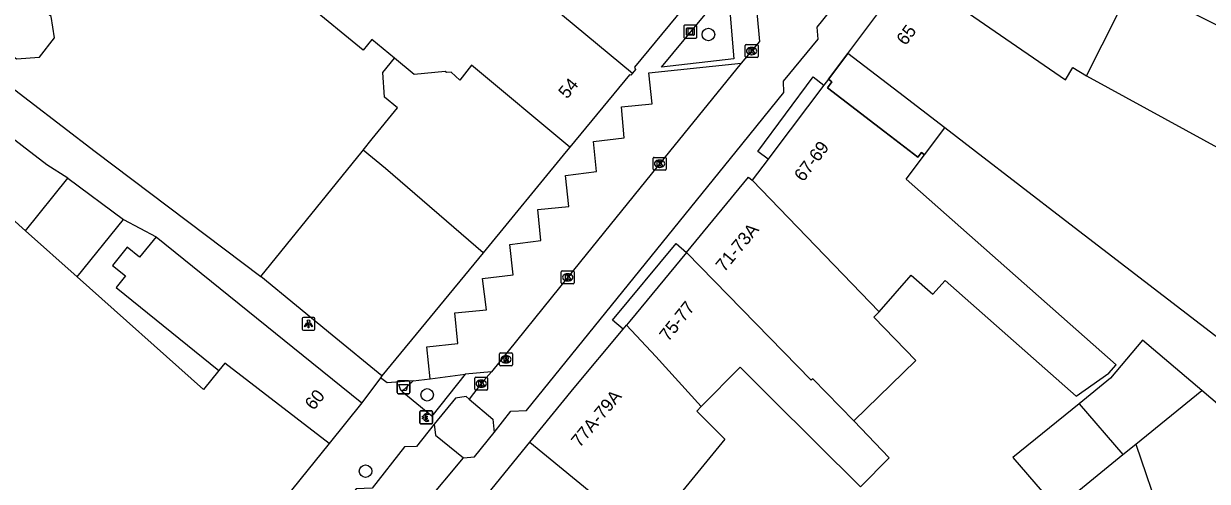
# Model space of a CAD drawing. Extents: x 160664 to 161506, y 382245 to 383288.
# Drawn here: x 161006.2 to 161098.3, y 382974.3 to 383010 of the extents above; entities that cross this region are included whole.
import ezdxf

# ---------------------------------------------------------------- set-up
doc = ezdxf.new("R2010")
doc.units = 0
for name, color, linetype in [('IMGEO_Afvalbak', 7, 'Continuous'), ('IMGEO_Betaalautomaat', 7, 'Continuous'), ('IMGEO_Boom', 7, 'Continuous'), ('IMGEO_Kolk', 7, 'Continuous'), ('IMGEO_Kunstobject', 7, 'Continuous'), ('IMGEO_Lichtpunt', 7, 'Continuous'), ('IMGEO_Pand', 7, 'Continuous'), ('IMGEO_Pand_nummerreeks', 7, 'Continuous'), ('IMGEO_Pand_overbouw', 7, 'Continuous'), ('IMGEO_Parkeervlak_open', 7, 'Continuous'), ('IMGEO_Rioolput', 7, 'Continuous'), ('IMGEO_Voetpad_open', 7, 'Continuous'), ('IMGEO_Woonerf_open', 7, 'Continuous')]:
    doc.layers.add(name, color=color, linetype=linetype)

msp = doc.modelspace()

# ---------------------------------------------------------------- linework, layer by layer
at = {"layer": 'IMGEO_Afvalbak'}
for p, q in [((161035.276, 382981.266), (161035.276, 382982.066)), ((161035.276, 382982.066), (161035.276, 382981.266)), ((161035.376, 382982.166), (161036.166, 382982.166)), ((161036.166, 382982.166), (161035.376, 382982.166)), ((161036.266, 382982.066), (161036.266, 382981.266)), ((161036.266, 382981.266), (161036.266, 382982.066)), ((161036.166, 382981.166), (161035.376, 382981.166)), ((161035.376, 382981.166), (161036.166, 382981.166))]:
    msp.add_line(p, q, dxfattribs=at)
msp.add_lwpolyline([(161035.419, 382981.88), (161036.123, 382981.88), (161035.974, 382981.41), (161035.568, 382981.41), (161035.419, 382981.88)], dxfattribs=at)
for centre, start, end in [((161035.376, 382982.066), 90, 180), ((161035.376, 382982.066), 90, 180), ((161036.166, 382982.066), 0, 90), ((161036.166, 382982.066), 360, 90), ((161035.376, 382981.266), 180, 270), ((161035.376, 382981.266), 180, 270), ((161036.166, 382981.266), 270, 0), ((161036.166, 382981.266), 270, 0)]:
    msp.add_arc(centre, 0.1, start, end, dxfattribs=at)
at = {"layer": 'IMGEO_Betaalautomaat'}
for p, q in [((161037.119, 382979.828), (161037.96, 382979.828)), ((161037.96, 382979.828), (161037.119, 382979.828)), ((161037.044, 382978.904), (161037.044, 382979.745)), ((161037.044, 382979.745), (161037.044, 382978.904)), ((161037.327, 382979.292), (161037.327, 382979.36)), ((161037.448, 382979.36), (161037.448, 382979.292)), ((161037.706, 382979.633), (161037.689, 382979.533)), ((161037.693, 382979.127), (161037.715, 382979.04)), ((161038.043, 382979.754), (161038.043, 382978.913)), ((161038.043, 382978.913), (161038.043, 382979.754)), ((161037.969, 382978.829), (161037.128, 382978.829)), ((161037.128, 382978.829), (161037.969, 382978.829))]:
    msp.add_line(p, q, dxfattribs=at)
for points in [[(161037.327, 382979.36), (161037.258, 382979.36), (161037.258, 382979.429), (161037.337, 382979.429)], [(161037.332, 382979.223), (161037.258, 382979.223), (161037.258, 382979.292), (161037.327, 382979.292)], [(161037.459, 382979.429), (161037.606, 382979.429), (161037.606, 382979.36), (161037.448, 382979.36)], [(161037.448, 382979.292), (161037.606, 382979.292), (161037.606, 382979.223), (161037.462, 382979.223)]]:
    msp.add_lwpolyline(points, dxfattribs=at)
for centre, radius, start, end in [((161037.122, 382979.751), 0.0779, 92.4484, 184.28452), ((161037.122, 382979.751), 0.0779, 92.4484, 184.28452), ((161037.966, 382979.751), 0.0779, 2.4484, 94.28452), ((161037.966, 382979.751), 0.0779, 2.4484, 94.28452), ((161037.122, 382978.907), 0.0779, 182.4484, 274.28452), ((161037.122, 382978.907), 0.0779, 182.4484, 274.28452), ((161037.593, 382979.278), 0.267, 191.80956, 297.03891), ((161037.62, 382979.353), 0.293, 73.01398, 165.01395), ((161037.626, 382979.366), 0.179, 69.32359, 159.56827), ((161037.626, 382979.293), 0.179, 202.76249, 291.86925), ((161037.966, 382978.907), 0.0779, 272.4484, 4.28452), ((161037.966, 382978.907), 0.0779, 272.4484, 4.28452)]:
    msp.add_arc(centre, radius, start, end, dxfattribs=at)
at = {"layer": 'IMGEO_Boom'}
for centre in [(161059.496, 383009.112), (161037.616, 382981.074), (161032.826, 382975.136)]:
    msp.add_circle(centre, 0.489, dxfattribs=at)
at = {"layer": 'IMGEO_Kolk'}
for p, q in [((161062.354, 383007.394), (161062.354, 383008.246)), ((161062.429, 383008.32), (161063.281, 383008.32)), ((161062.865, 383007.54), (161062.84, 383007.54)), ((161062.842, 383008.1), (161062.867, 383008.1)), ((161063.355, 383008.246), (161063.355, 383007.394)), ((161063.281, 383007.32), (161062.429, 383007.32)), ((161055.201, 382998.627), (161055.201, 382999.479)), ((161055.276, 382999.553), (161056.128, 382999.553)), ((161055.689, 382999.333), (161055.714, 382999.333)), ((161056.202, 382999.479), (161056.202, 382998.627)), ((161056.128, 382998.553), (161055.276, 382998.553)), ((161055.712, 382998.773), (161055.687, 382998.773)), ((161048.052, 382989.797), (161048.052, 382990.649)), ((161048.127, 382990.723), (161048.979, 382990.723)), ((161048.563, 382989.943), (161048.538, 382989.943)), ((161048.54, 382990.503), (161048.565, 382990.503)), ((161049.053, 382990.649), (161049.053, 382989.797)), ((161048.979, 382989.723), (161048.127, 382989.723)), ((161041.322, 382981.523), (161041.322, 382982.375)), ((161041.397, 382982.449), (161042.249, 382982.449)), ((161041.833, 382981.669), (161041.808, 382981.669)), ((161041.81, 382982.229), (161041.835, 382982.229)), ((161042.323, 382982.375), (161042.323, 382981.523)), ((161042.249, 382981.449), (161041.397, 382981.449))]:
    msp.add_line(p, q, dxfattribs=at)
for points in [[(161062.354, 383007.394), (161062.354, 383008.246)], [(161062.429, 383008.32), (161063.281, 383008.32)], [(161062.675, 383008.02), (161062.798, 383008.02), (161062.798, 383007.869), (161062.928, 383008.02), (161063.092, 383008.02), (161062.946, 383007.869), (161063.099, 383007.62), (161062.947, 383007.62), (161062.862, 383007.784), (161062.798, 383007.717), (161062.798, 383007.62), (161062.675, 383007.62), (161062.675, 383008.02)], [(161063.355, 383008.246), (161063.355, 383007.394)], [(161063.281, 383007.32), (161062.429, 383007.32)], [(161055.201, 382998.627), (161055.201, 382999.479)], [(161055.276, 382999.553), (161056.128, 382999.553)], [(161055.522, 382999.253), (161055.645, 382999.253), (161055.645, 382999.102), (161055.775, 382999.253), (161055.939, 382999.253), (161055.793, 382999.102), (161055.946, 382998.853), (161055.794, 382998.853), (161055.709, 382999.017), (161055.645, 382998.95), (161055.645, 382998.853), (161055.522, 382998.853), (161055.522, 382999.253)], [(161056.202, 382999.479), (161056.202, 382998.627)], [(161056.128, 382998.553), (161055.276, 382998.553)], [(161048.052, 382989.797), (161048.052, 382990.649)], [(161048.127, 382990.723), (161048.979, 382990.723)], [(161048.373, 382990.423), (161048.496, 382990.423), (161048.496, 382990.272), (161048.626, 382990.423), (161048.79, 382990.423), (161048.644, 382990.272), (161048.797, 382990.023), (161048.645, 382990.023), (161048.56, 382990.187), (161048.496, 382990.12), (161048.496, 382990.023), (161048.373, 382990.023), (161048.373, 382990.423)], [(161049.053, 382990.649), (161049.053, 382989.797)], [(161048.979, 382989.723), (161048.127, 382989.723)], [(161041.322, 382981.523), (161041.322, 382982.375)], [(161041.397, 382982.449), (161042.249, 382982.449)], [(161041.643, 382982.149), (161041.766, 382982.149), (161041.766, 382981.998), (161041.896, 382982.149), (161042.06, 382982.149), (161041.914, 382981.998), (161042.067, 382981.749), (161041.915, 382981.749), (161041.83, 382981.913), (161041.766, 382981.846), (161041.766, 382981.749), (161041.643, 382981.749), (161041.643, 382982.149)], [(161042.323, 382982.375), (161042.323, 382981.523)], [(161042.249, 382981.449), (161041.397, 382981.449)]]:
    msp.add_lwpolyline(points, dxfattribs=at)
for centre, start, end in [((161062.431, 383008.244), 91.55205, 178.44795), ((161062.431, 383008.244), 91.55205, 178.44795), ((161063.279, 383008.244), 1.55205, 88.44795), ((161063.279, 383008.244), 1.55205, 88.44795), ((161062.431, 383007.396), 181.55205, 268.44795), ((161062.431, 383007.396), 181.55205, 268.44795), ((161063.279, 383007.396), 271.55205, 358.44795), ((161063.279, 383007.396), 271.55205, 358.44795), ((161055.278, 382999.477), 91.55205, 178.44795), ((161055.278, 382999.477), 91.55205, 178.44795), ((161056.126, 382999.477), 1.55205, 88.44795), ((161056.126, 382999.477), 1.55205, 88.44795), ((161055.278, 382998.629), 181.55205, 268.44795), ((161055.278, 382998.629), 181.55205, 268.44795), ((161056.126, 382998.629), 271.55205, 358.44795), ((161056.126, 382998.629), 271.55205, 358.44795), ((161048.129, 382990.647), 91.55205, 178.44795), ((161048.129, 382990.647), 91.55205, 178.44795), ((161048.977, 382990.647), 1.55205, 88.44795), ((161048.977, 382990.647), 1.55205, 88.44795), ((161048.129, 382989.799), 181.55205, 268.44795), ((161048.129, 382989.799), 181.55205, 268.44795), ((161048.977, 382989.799), 271.55205, 358.44795), ((161048.977, 382989.799), 271.55205, 358.44795), ((161041.399, 382982.373), 91.55205, 178.44795), ((161041.399, 382982.373), 91.55205, 178.44795), ((161042.247, 382982.373), 1.55205, 88.44795), ((161042.247, 382982.373), 1.55205, 88.44795), ((161041.399, 382981.525), 181.55205, 268.44795), ((161041.399, 382981.525), 181.55205, 268.44795), ((161042.247, 382981.525), 271.55205, 358.44795), ((161042.247, 382981.525), 271.55205, 358.44795)]:
    msp.add_arc(centre, 0.0765, start, end, dxfattribs=at)
for centre, major_axis, ratio, start_param, end_param in [((161062.841, 383007.82), (-0.387, 0.002), 0.722429, 4.712389, 7.853982), ((161062.866, 383007.82), (-0.39, 0.002), 0.717154, 1.570796, 4.712389), ((161055.688, 382999.053), (-0.387, 0.002), 0.722429, 4.712389, 7.853982), ((161055.713, 382999.053), (-0.39, 0.002), 0.717154, 1.570796, 4.712389), ((161048.539, 382990.223), (-0.387, 0.002), 0.722429, 4.712389, 7.853982), ((161048.564, 382990.223), (-0.39, 0.002), 0.717154, 1.570796, 4.712389), ((161041.809, 382981.949), (-0.387, 0.002), 0.722429, 4.712389, 7.853982), ((161041.834, 382981.949), (-0.39, 0.002), 0.717154, 1.570796, 4.712389)]:
    msp.add_ellipse(centre, major_axis=major_axis, ratio=ratio, start_param=start_param, end_param=end_param, dxfattribs=at)
at = {"layer": 'IMGEO_Kunstobject'}
for p, q in [((161057.588, 383009.748), (161057.588, 383008.907)), ((161057.588, 383009.748), (161057.588, 383008.907)), ((161058.504, 383009.832), (161057.663, 383009.832)), ((161058.504, 383009.832), (161057.663, 383009.832)), ((161057.802, 383009.096), (161057.802, 383009.57)), ((161057.852, 383009.62), (161058.326, 383009.62)), ((161057.882, 383009.52), (161057.882, 383009.146)), ((161058.276, 383009.54), (161057.902, 383009.54)), ((161058.296, 383009.146), (161058.296, 383009.52)), ((161058.376, 383009.57), (161058.376, 383009.096)), ((161058.588, 383008.916), (161058.588, 383009.757)), ((161058.588, 383008.916), (161058.588, 383009.757)), ((161057.672, 383008.832), (161058.513, 383008.832)), ((161057.672, 383008.832), (161058.513, 383008.832)), ((161058.326, 383009.046), (161057.852, 383009.046)), ((161057.902, 383009.126), (161058.276, 383009.126))]:
    msp.add_line(p, q, dxfattribs=at)
for centre, radius, start, end in [((161057.666, 383009.754), 0.0779, 92.4484, 184.28452), ((161057.666, 383009.754), 0.0779, 92.4484, 184.28452), ((161057.852, 383009.57), 0.05, 90, 180), ((161057.902, 383009.52), 0.02, 90, 180), ((161058.276, 383009.52), 0.02, 360, 90), ((161058.326, 383009.57), 0.05, 360, 90), ((161058.51, 383009.754), 0.0779, 2.4484, 94.28452), ((161058.51, 383009.754), 0.0779, 2.4484, 94.28452), ((161057.666, 383008.91), 0.0779, 182.4484, 274.28452), ((161057.666, 383008.91), 0.0779, 182.4484, 274.28452), ((161057.852, 383009.096), 0.05, 180, 270), ((161057.902, 383009.146), 0.02, 180, 270), ((161058.276, 383009.146), 0.02, 270, 0), ((161058.326, 383009.096), 0.05, 270, 0), ((161058.51, 383008.91), 0.0779, 272.4484, 4.28452), ((161058.51, 383008.91), 0.0779, 272.4484, 4.28452)]:
    msp.add_arc(centre, radius, start, end, dxfattribs=at)
at = {"layer": 'IMGEO_Lichtpunt'}
for p, q in [((161027.895, 382987.005), (161027.895, 382986.198)), ((161027.895, 382987.005), (161027.895, 382986.198)), ((161028.797, 382987.1), (161027.989, 382987.1)), ((161028.797, 382987.1), (161027.989, 382987.1)), ((161028.891, 382986.198), (161028.891, 382987.005)), ((161028.891, 382986.198), (161028.891, 382987.005)), ((161027.989, 382986.104), (161028.797, 382986.104)), ((161027.989, 382986.104), (161028.797, 382986.104))]:
    msp.add_line(p, q, dxfattribs=at)
for points in [[(161028.269, 382986.669), (161028.308, 382986.641), (161028.12, 382986.379), (161028.082, 382986.406), (161028.269, 382986.669)], [(161028.371, 382986.621), (161028.418, 382986.621), (161028.418, 382986.299), (161028.371, 382986.299), (161028.371, 382986.621)], [(161028.481, 382986.641), (161028.519, 382986.668), (161028.706, 382986.406), (161028.667, 382986.378), (161028.481, 382986.641)]]:
    msp.add_lwpolyline(points, dxfattribs=at)
msp.add_circle((161028.394, 382986.803), 0.0994, dxfattribs=at)
for centre, start, end in [((161027.989, 382987.005), 90, 180), ((161027.989, 382987.005), 90, 180), ((161028.797, 382987.005), 0, 90), ((161028.797, 382987.005), 0, 90), ((161027.989, 382986.198), 180, 270), ((161027.989, 382986.198), 180, 270), ((161028.797, 382986.198), 270, 0), ((161028.797, 382986.198), 270, 360)]:
    msp.add_arc(centre, 0.0946, start, end, dxfattribs=at)
at = {"layer": 'IMGEO_Pand'}
for points in [[(161035.066, 383007.264), (161033.307, 383008.711), (161032.628, 383007.886), (161028.208, 383011.521), (161028.345, 383011.687), (161031.521, 383015.548), (161033.334, 383015.724), (161034.176, 383015.032), (161037.672, 383019.283), (161043.618, 383014.393)], [(161088.895, 383005.883), (161092.523, 383013.112), (161096.995, 383010.875), (161109.256, 383004.742), (161116.889, 383002.165), (161120.977, 383008.51), (161114.302, 383011.074), (161114.043, 383010.4), (161106.846, 383013.164), (161108.705, 383018.003), (161133.815, 383008.358), (161128.422, 383000), (161127.727, 382998.923)], [(161043.618, 383014.393), (161053.588, 383006.099)], [(161070.33, 383007.638), (161075.075, 383013.995)], [(161075.075, 383013.995), (161087.272, 383005.575), (161087.844, 383006.553), (161088.895, 383005.883)], [(161059.678, 383013.78), (161053.757, 383006.58), (161053.828, 383006.391), (161053.588, 383006.099)], [(161004.266, 383010.049), (161004.551, 383008.078), (161005.669, 383007.226), (161007.455, 383007.339), (161008.62, 383008.85), (161008.38, 383010.504), (161007.123, 383011.574), (161005.675, 383011.484), (161005.355, 383011.463), (161004.266, 383010.049)], [(161112.503, 382993), (161109.592, 382989.209), (161103.93, 382981.836), (161087.275, 382994.626), (161080.277, 383000), (161077.886, 383001.836), (161074.296, 383004.593), (161070.33, 383007.638)], [(161032.638, 383000.108), (161033.349, 383000.985), (161035.309, 383003.404), (161034.299, 383004.235), (161034.173, 383006.162), (161035.066, 383007.264)], [(161048.722, 383000.343), (161041.064, 383006.713), (161040.172, 383005.56), (161039.477, 383006.191), (161039.115, 383006.165), (161039.021, 383006.242), (161036.596, 383006.006), (161035.066, 383007.264)], [(161053.588, 383006.099), (161053.468, 383005.953), (161053.349, 383005.973), (161048.722, 383000.343)], [(161068.825, 383005.627), (161068.48, 383005.17)], [(161072.789, 382987.524), (161075.277, 382990.391), (161076.956, 382988.908), (161077.903, 382989.981), (161088.113, 382980.966), (161090.643, 382982.77), (161091.222, 382983.4), (161074.875, 382997.85), (161076.314, 382999.756), (161076.076, 382999.939), (161075.791, 382999.555), (161068.758, 383004.956), (161069.093, 383005.422), (161068.825, 383005.627)], [(161088.895, 383005.883), (161099.676, 383000), (161112.503, 382993)], [(161068.48, 383005.17), (161064.578, 383000), (161064.135, 382999.413)], [(161024.693, 382990.287), (161032.566, 383000), (161032.638, 383000.108)], [(161041.972, 382992.13), (161034.381, 382998.684), (161032.638, 383000.108)], [(161048.722, 383000.343), (161048.44, 383000), (161041.972, 382992.13)], [(161064.135, 382999.413), (161062.907, 382997.786)], [(161006.384, 382993.846), (161001.288, 382998.396), (161000, 382996.936), (160993.87, 382988.888), (160992.195, 382990.157)], [(161006.384, 382993.846), (161009.678, 382997.924)], [(161009.678, 382997.924), (161013.992, 382994.722)], [(161057.794, 382992.16), (161062.614, 382998.01), (161062.907, 382997.786)], [(161062.907, 382997.786), (161072.789, 382987.524)], [(161010.392, 382990.267), (161013.992, 382994.722)], [(161010.392, 382990.267), (161006.384, 382993.846)], [(161016.538, 382993.373), (161015.252, 382991.781), (161014.291, 382992.558), (161013.151, 382991.147), (161014.149, 382990.341), (161013.416, 382989.433), (161021.424, 382982.963)], [(161016.538, 382993.373), (161028.645, 382983.591), (161032.535, 382980.449)], [(161041.972, 382992.13), (161034.101, 382982.551)], [(161057.794, 382992.16), (161053.393, 382986.818), (161053.125, 382986.493)], [(161070.797, 382979.043), (161067.619, 382982.325), (161067.484, 382982.226), (161057.794, 382992.16)], [(161021.424, 382982.963), (161020.229, 382981.484), (161010.392, 382990.267)], [(161034.101, 382982.551), (161030.239, 382985.727), (161024.693, 382990.287)], [(161072.789, 382987.524), (161072.376, 382987.108), (161075.64, 382983.749), (161070.797, 382979.043)], [(161052.853, 382986.173), (161053.125, 382986.493)], [(161053.125, 382986.493), (161055.404, 382984.052), (161058.936, 382980.168)], [(161045.598, 382977.395), (161049.049, 382981.63), (161052.853, 382986.173)], [(161097.867, 382981.406), (161093.264, 382985.322), (161090.76, 382982.369), (161088.324, 382980.389)], [(161029.997, 382977.303), (161021.889, 382983.539), (161021.424, 382982.963)], [(161058.936, 382980.168), (161061.974, 382983.222), (161064.36, 382980.849), (161071.315, 382973.932), (161073.56, 382976.189), (161070.797, 382979.043)], [(161092.735, 382977.235), (161097.867, 382981.406)], [(161092.735, 382977.235), (161094.742, 382971.374), (161104.322, 382975.914), (161097.867, 382981.406)], [(161032.535, 382980.449), (161029.997, 382977.303)], [(161058.936, 382980.168), (161058.586, 382979.816), (161060.765, 382977.621), (161057.751, 382973.921), (161054.585, 382970.035)], [(161088.324, 382980.389), (161083.179, 382976.209), (161086.592, 382972.244), (161091.737, 382976.425)], [(161088.324, 382980.389), (161091.737, 382976.425)], [(161029.997, 382977.303), (161015.758, 382959.65)], [(161041.379, 382972.777), (161041.718, 382973.193), (161041.992, 382972.97), (161045.598, 382977.395)], [(161045.598, 382977.395), (161050.517, 382973.367), (161051.004, 382972.968), (161054.585, 382970.035)], [(161091.737, 382976.425), (161092.735, 382977.235)]]:
    msp.add_lwpolyline(points, dxfattribs=at)
at = {"layer": 'IMGEO_Pand_overbouw'}
msp.add_lwpolyline([(161076.314, 382999.756), (161077.886, 383001.836), (161074.296, 383004.593), (161070.33, 383007.638), (161068.825, 383005.627), (161069.093, 383005.422), (161068.758, 383004.956), (161072.449, 383002.124), (161075.217, 383000), (161075.791, 382999.555), (161076.076, 382999.939)], close=True, dxfattribs=at)
at = {"layer": 'IMGEO_Parkeervlak_open'}
for points in [[(161062.045, 383006.867), (161056.472, 383000), (161048.554, 382990.222), (161042.624, 382982.867)], [(161037.85, 382982.334), (161040.584, 382982.696)]]:
    msp.add_lwpolyline(points, dxfattribs=at)
at = {"layer": 'IMGEO_Rioolput'}
for p, q in [((161043.249, 382983.416), (161043.249, 382984.268)), ((161043.324, 382984.342), (161044.176, 382984.342)), ((161043.76, 382983.562), (161043.735, 382983.562)), ((161043.737, 382984.122), (161043.762, 382984.122)), ((161044.25, 382984.268), (161044.25, 382983.416)), ((161044.176, 382983.342), (161043.324, 382983.342))]:
    msp.add_line(p, q, dxfattribs=at)
for points in [[(161043.249, 382983.416), (161043.249, 382984.268)], [(161043.324, 382984.342), (161044.176, 382984.342)], [(161043.838, 382984.04), (161043.586, 382984.042), (161043.586, 382983.642)], [(161043.586, 382983.642), (161043.71, 382983.642), (161043.71, 382983.804), (161043.721, 382983.804)], [(161043.764, 382983.961), (161043.71, 382983.961), (161043.71, 382983.88)], [(161043.71, 382983.88), (161043.762, 382983.88)], [(161043.768, 382983.775), (161043.839, 382983.642), (161043.979, 382983.642), (161043.914, 382983.768)], [(161044.25, 382984.268), (161044.25, 382983.416)], [(161044.176, 382983.342), (161043.324, 382983.342)]]:
    msp.add_lwpolyline(points, dxfattribs=at)
for centre, radius, start, end in [((161043.326, 382984.266), 0.0765, 91.55205, 178.44795), ((161043.326, 382984.266), 0.0765, 91.55205, 178.44795), ((161043.72, 382983.751), 0.0533, 26.02933, 88.69889), ((161043.746, 382984.069), 0.19, 274.7715, 282.96867), ((161043.77, 382983.865), 0.0964, 77.00612, 93.18647), ((161043.784, 382983.922), 0.0378, 276.66336, 79.67722), ((161043.837, 382983.93), 0.109, 350.36119, 89.41601), ((161043.835, 382983.93), 0.112, 277.58423, 350.98172), ((161043.819, 382983.715), 0.108, 29.51342, 73.79051), ((161044.174, 382984.266), 0.0765, 1.55205, 88.44795), ((161044.174, 382984.266), 0.0765, 1.55205, 88.44795), ((161043.326, 382983.418), 0.0765, 181.55205, 268.44795), ((161043.326, 382983.418), 0.0765, 181.55205, 268.44795), ((161044.174, 382983.418), 0.0765, 271.55205, 358.44795), ((161044.174, 382983.418), 0.0765, 271.55205, 358.44795)]:
    msp.add_arc(centre, radius, start, end, dxfattribs=at)
for centre, major_axis, ratio, start_param, end_param in [((161043.736, 382983.842), (-0.387, 0.002), 0.722429, 4.712389, 7.853982), ((161043.761, 382983.842), (-0.39, 0.002), 0.717154, 1.570796, 4.712389)]:
    msp.add_ellipse(centre, major_axis=major_axis, ratio=ratio, start_param=start_param, end_param=end_param, dxfattribs=at)
at = {"layer": 'IMGEO_Voetpad_open'}
for points in [[(161042.826, 382978.151), (161044.125, 382979.819), (161045.357, 382979.851), (161061.654, 383000), (161065.375, 383004.601), (161065.342, 383005.477), (161068.039, 383008.738), (161067.943, 383009.691), (161072.199, 383014.962), (161072.068, 383016.448), (161073.465, 383018.514)], [(161061.708, 383016.259), (161062.859, 383015.353), (161063.468, 383008.572), (161062.045, 383006.867)], [(161061.476, 383007.21), (161055.845, 383006.558), (161061.005, 383012.821), (161061.476, 383007.21)], [(161001.496, 383007.901), (161011.804, 383000), (161024.693, 382990.287)], [(161068.825, 383005.627), (161070.33, 383007.638)], [(161037.85, 382982.334), (161037.595, 382984.801), (161040.002, 382985.06), (161039.774, 382987.465), (161042.222, 382987.697), (161041.918, 382990.125), (161044.307, 382990.424), (161044.04, 382992.781), (161046.472, 382993.089), (161046.226, 382995.489), (161048.627, 382995.74), (161048.391, 382998.153), (161050.784, 382998.443), (161050.636, 383000), (161050.561, 383000.794), (161052.944, 383001.061), (161052.724, 383003.47), (161055.125, 383003.706), (161054.863, 383006.126), (161062.045, 383006.867)], [(161064.135, 382999.413), (161063.342, 383000), (161067.647, 383005.81), (161068.48, 383005.17)], [(161009.678, 382997.924), (161008.031, 382998.962), (161002.601, 383003.14), (161002.198, 383002.638), (161001.583, 383001.871)], [(161013.992, 382994.722), (161016.538, 382993.373)], [(161052.853, 382986.173), (161052.028, 382986.881), (161056.992, 382992.845), (161057.794, 382992.16)], [(161034.101, 382982.551), (161033.994, 382982.407)], [(161040.584, 382982.696), (161037.983, 382979.425), (161035.648, 382981.344), (161036.542, 382982.161)], [(161042.624, 382982.867), (161040.584, 382982.696)], [(161042.624, 382982.867), (161041.825, 382981.949), (161040.888, 382980.746)], [(161033.994, 382982.407), (161032.535, 382980.449)], [(161036.542, 382982.161), (161034.519, 382982.001), (161033.994, 382982.407)], [(161036.542, 382982.161), (161037.85, 382982.334)], [(161040.888, 382980.746), (161040.65, 382980.949), (161039.83, 382980.829), (161038.171, 382978.793)], [(161038.171, 382978.793), (161036.798, 382977.065), (161035.859, 382977.032), (161033.352, 382973.821), (161032.095, 382973.764), (161028.657, 382969.499)], [(161040.453, 382976.167), (161041.295, 382976.256), (161042.826, 382978.151)], [(161035.13, 382970.603), (161036.587, 382972.42), (161037.407, 382972.543), (161040.453, 382976.167)]]:
    msp.add_lwpolyline(points, dxfattribs=at)
at = {"layer": 'IMGEO_Woonerf_open'}
for points in [[(161040.888, 382980.746), (161042.728, 382979.183), (161042.826, 382978.151)], [(161038.171, 382978.793), (161038.274, 382977.93), (161040.453, 382976.167)]]:
    msp.add_lwpolyline(points, dxfattribs=at)

# ---------------------------------------------------------------- texts
at = {"layer": 'IMGEO_Pand_nummerreeks'}
for s, rotation, p in [('65', 53.26216, (161074.836, 383008.193)), ('54', 50.58644, (161048.504, 383004.047)), ('67-69', 52.95849, (161066.874, 382997.595)), ('71-73A', 50.51491, (161060.741, 382990.578)), ('75-77', 51.51242, (161056.371, 382985.162)), ('60', 51.10554, (161028.788, 382979.818)), ('77A-79A', 50.43175, (161049.494, 382976.926))]:
    msp.add_text(s, height=1, rotation=rotation, dxfattribs=at).set_placement(p)

doc.saveas('drawing.dxf')
